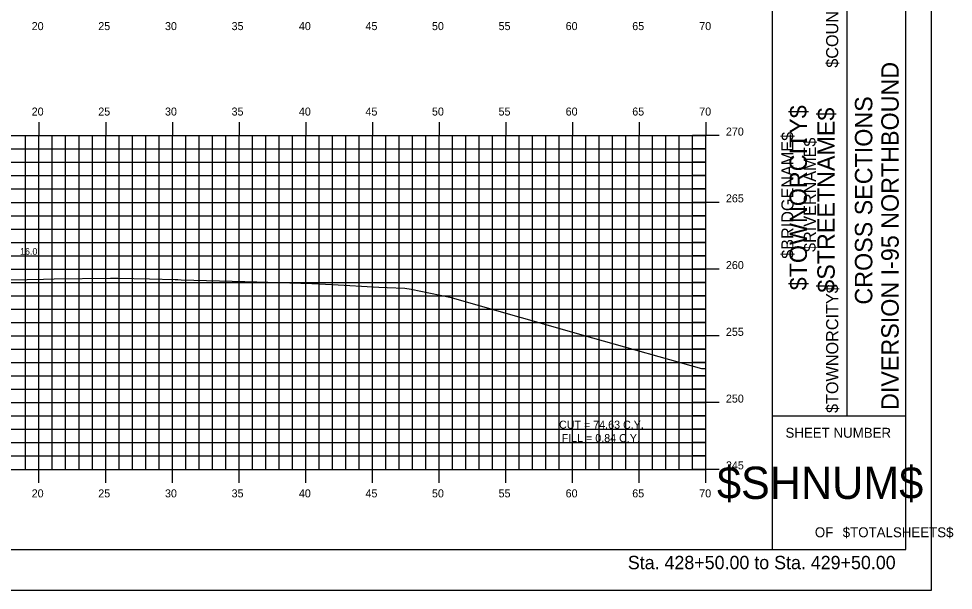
# Model space of a CAD drawing. Extents: x 1160718 to 1173142, y 616002 to 617630.
# Drawn here: x 1171089.7 to 1171159.7, y 616613.9 to 616656.7 of the extents above; entities that cross this region are included whole.
import ezdxf

# ---------------------------------------------------------------- set-up
doc = ezdxf.new("R2010")
doc.units = 0
for name, color, linetype in [('ANNOTATION', 7, 'Continuous'), ('BORDER', 7, 'Continuous'), ('BRIDGE_TITLE', 7, 'Continuous'), ('H_V ANNOTATION', 7, 'Continuous'), ('HIGHWAY_TITLE', 7, 'Continuous'), ('MAJOR', 7, 'Continuous'), ('MINOR', 7, 'Continuous'), ('PLOT BOUNDARY', 7, 'Continuous'), ('S_Roadway_Centerline', 7, 'Continuous')]:
    doc.layers.add(name, color=color, linetype=linetype)

msp = doc.modelspace()

# ---------------------------------------------------------------- linework, layer by layer
at = {"layer": 'BORDER'}
for p, q in [((1171146.177, 616616.931), (1171146.177, 616721.931)), ((1171156.177, 616616.931), (1171156.177, 616721.931)), ((1171151.768, 616626.931), (1171151.768, 616661.931)), ((1171146.177, 616626.931), (1171156.177, 616626.931)), ((1170996.177, 616616.928), (1171156.177, 616616.928))]:
    msp.add_line(p, q, dxfattribs=at)
at = {"layer": 'MAJOR'}
for p, q in [((1171091.177, 616648.93), (1171091.177, 616647.928)), ((1171096.177, 616648.93), (1171096.177, 616647.928)), ((1171101.177, 616648.93), (1171101.177, 616647.928)), ((1171106.177, 616648.93), (1171106.177, 616647.928)), ((1171111.177, 616648.93), (1171111.177, 616647.928)), ((1171116.177, 616648.93), (1171116.177, 616647.928)), ((1171121.177, 616648.93), (1171121.177, 616647.928)), ((1171126.177, 616648.93), (1171126.177, 616647.928)), ((1171131.177, 616648.93), (1171131.177, 616647.928)), ((1171136.177, 616648.93), (1171136.177, 616647.928)), ((1171141.177, 616648.93), (1171141.177, 616647.928)), ((1171001.177, 616647.928), (1171141.177, 616647.928)), ((1171001.177, 616647.928), (1171141.177, 616647.928)), ((1171091.177, 616622.928), (1171091.177, 616647.928)), ((1171096.177, 616622.928), (1171096.177, 616647.928)), ((1171101.177, 616622.928), (1171101.177, 616647.928)), ((1171106.177, 616622.928), (1171106.177, 616647.928)), ((1171111.177, 616622.928), (1171111.177, 616647.928)), ((1171116.177, 616622.928), (1171116.177, 616647.928)), ((1171121.177, 616622.928), (1171121.177, 616647.928)), ((1171126.177, 616622.928), (1171126.177, 616647.928)), ((1171131.177, 616622.928), (1171131.177, 616647.928)), ((1171136.177, 616622.928), (1171136.177, 616647.928)), ((1171142.179, 616647.928), (1171140.175, 616647.928)), ((1171141.177, 616622.928), (1171141.177, 616647.928)), ((1171141.177, 616622.928), (1171141.177, 616647.928)), ((1171001.177, 616642.928), (1171141.177, 616642.928)), ((1171142.179, 616642.928), (1171140.175, 616642.928)), ((1171001.177, 616637.928), (1171141.177, 616637.928)), ((1171142.179, 616637.928), (1171140.175, 616637.928)), ((1171001.177, 616632.928), (1171141.177, 616632.928)), ((1171142.179, 616632.928), (1171140.175, 616632.928)), ((1171001.177, 616627.928), (1171141.177, 616627.928)), ((1171142.179, 616627.928), (1171140.175, 616627.928)), ((1171001.177, 616622.928), (1171141.177, 616622.928)), ((1171001.177, 616622.928), (1171141.177, 616622.928)), ((1171091.177, 616621.926), (1171091.177, 616622.928)), ((1171096.177, 616621.926), (1171096.177, 616622.928)), ((1171101.177, 616621.926), (1171101.177, 616622.928)), ((1171106.177, 616621.926), (1171106.177, 616622.928)), ((1171111.177, 616621.926), (1171111.177, 616622.928)), ((1171116.177, 616621.926), (1171116.177, 616622.928)), ((1171121.177, 616621.926), (1171121.177, 616622.928)), ((1171126.177, 616621.926), (1171126.177, 616622.928)), ((1171131.177, 616621.926), (1171131.177, 616622.928)), ((1171136.177, 616621.926), (1171136.177, 616622.928)), ((1171142.179, 616622.928), (1171140.175, 616622.928)), ((1171141.177, 616621.926), (1171141.177, 616622.928))]:
    msp.add_line(p, q, dxfattribs=at)
at = {"layer": 'MINOR'}
for p, q in [((1171090.177, 616622.928), (1171090.177, 616647.928)), ((1171092.177, 616622.928), (1171092.177, 616647.928)), ((1171093.177, 616622.928), (1171093.177, 616647.928)), ((1171094.177, 616622.928), (1171094.177, 616647.928)), ((1171095.177, 616622.928), (1171095.177, 616647.928)), ((1171097.177, 616622.928), (1171097.177, 616647.928)), ((1171098.177, 616622.928), (1171098.177, 616647.928)), ((1171099.177, 616622.928), (1171099.177, 616647.928)), ((1171100.177, 616622.928), (1171100.177, 616647.928)), ((1171102.177, 616622.928), (1171102.177, 616647.928)), ((1171103.177, 616622.928), (1171103.177, 616647.928)), ((1171104.177, 616622.928), (1171104.177, 616647.928)), ((1171105.177, 616622.928), (1171105.177, 616647.928)), ((1171107.177, 616622.928), (1171107.177, 616647.928)), ((1171108.177, 616622.928), (1171108.177, 616647.928)), ((1171109.177, 616622.928), (1171109.177, 616647.928)), ((1171110.177, 616622.928), (1171110.177, 616647.928)), ((1171112.177, 616622.928), (1171112.177, 616647.928)), ((1171113.177, 616622.928), (1171113.177, 616647.928)), ((1171114.177, 616622.928), (1171114.177, 616647.928)), ((1171115.177, 616622.928), (1171115.177, 616647.928)), ((1171117.177, 616622.928), (1171117.177, 616647.928)), ((1171118.177, 616622.928), (1171118.177, 616647.928)), ((1171119.177, 616622.928), (1171119.177, 616647.928)), ((1171120.177, 616622.928), (1171120.177, 616647.928)), ((1171122.177, 616622.928), (1171122.177, 616647.928)), ((1171123.177, 616622.928), (1171123.177, 616647.928)), ((1171124.177, 616622.928), (1171124.177, 616647.928)), ((1171125.177, 616622.928), (1171125.177, 616647.928)), ((1171127.177, 616622.928), (1171127.177, 616647.928)), ((1171128.177, 616622.928), (1171128.177, 616647.928)), ((1171129.177, 616622.928), (1171129.177, 616647.928)), ((1171130.177, 616622.928), (1171130.177, 616647.928)), ((1171132.177, 616622.928), (1171132.177, 616647.928)), ((1171133.177, 616622.928), (1171133.177, 616647.928)), ((1171134.177, 616622.928), (1171134.177, 616647.928)), ((1171135.177, 616622.928), (1171135.177, 616647.928)), ((1171137.177, 616622.928), (1171137.177, 616647.928)), ((1171138.177, 616622.928), (1171138.177, 616647.928)), ((1171139.177, 616622.928), (1171139.177, 616647.928)), ((1171140.177, 616622.928), (1171140.177, 616647.928)), ((1171001.177, 616646.928), (1171141.177, 616646.928)), ((1171141.177, 616646.928), (1171140.175, 616646.928)), ((1171001.177, 616645.928), (1171141.177, 616645.928)), ((1171141.177, 616645.928), (1171140.175, 616645.928)), ((1171001.177, 616644.928), (1171141.177, 616644.928)), ((1171141.177, 616644.928), (1171140.175, 616644.928)), ((1171001.177, 616643.928), (1171141.177, 616643.928)), ((1171141.177, 616643.928), (1171140.175, 616643.928)), ((1171001.177, 616641.928), (1171141.177, 616641.928)), ((1171141.177, 616641.928), (1171140.175, 616641.928)), ((1171001.177, 616640.928), (1171141.177, 616640.928)), ((1171141.177, 616640.928), (1171140.175, 616640.928)), ((1171001.177, 616639.928), (1171141.177, 616639.928)), ((1171141.177, 616639.928), (1171140.175, 616639.928)), ((1171001.177, 616638.928), (1171141.177, 616638.928)), ((1171141.177, 616638.928), (1171140.175, 616638.928)), ((1171001.177, 616636.928), (1171141.177, 616636.928)), ((1171141.177, 616636.928), (1171140.175, 616636.928)), ((1171001.177, 616635.928), (1171141.177, 616635.928)), ((1171141.177, 616635.928), (1171140.175, 616635.928)), ((1171001.177, 616634.928), (1171141.177, 616634.928)), ((1171141.177, 616634.928), (1171140.175, 616634.928)), ((1171001.177, 616633.928), (1171141.177, 616633.928)), ((1171141.177, 616633.928), (1171140.175, 616633.928)), ((1171001.177, 616631.928), (1171141.177, 616631.928)), ((1171141.177, 616631.928), (1171140.175, 616631.928)), ((1171001.177, 616630.928), (1171141.177, 616630.928)), ((1171141.177, 616630.928), (1171140.175, 616630.928)), ((1171001.177, 616629.928), (1171141.177, 616629.928)), ((1171141.177, 616629.928), (1171140.175, 616629.928)), ((1171001.177, 616628.928), (1171141.177, 616628.928)), ((1171141.177, 616628.928), (1171140.175, 616628.928)), ((1171001.177, 616626.928), (1171141.177, 616626.928)), ((1171141.177, 616626.928), (1171140.175, 616626.928)), ((1171001.177, 616625.928), (1171141.177, 616625.928)), ((1171141.177, 616625.928), (1171140.175, 616625.928)), ((1171001.177, 616624.928), (1171141.177, 616624.928)), ((1171141.177, 616624.928), (1171140.175, 616624.928)), ((1171001.177, 616623.928), (1171141.177, 616623.928)), ((1171141.177, 616623.928), (1171140.175, 616623.928))]:
    msp.add_line(p, q, dxfattribs=at)
at = {"layer": 'PLOT BOUNDARY'}
msp.add_lwpolyline([(1170988.084, 616613.869), (1171158.084, 616613.869), (1171158.084, 616723.869), (1170988.084, 616723.869)], close=True, dxfattribs=at)
at = {"layer": 'S_Roadway_Centerline'}
msp.add_lwpolyline([(1171087.785, 616637.11), (1171091.512, 616637.181), (1171092.311, 616637.192), (1171096.543, 616637.252), (1171096.558, 616637.252), (1171096.837, 616637.253), (1171097.091, 616637.246), (1171099.453, 616637.189), (1171101.389, 616637.142), (1171101.574, 616637.136), (1171101.843, 616637.129), (1171106.606, 616637.001), (1171107.511, 616636.976), (1171111.637, 616636.852), (1171113.181, 616636.765), (1171116.668, 616636.572), (1171117.287, 616636.551), (1171118.614, 616636.507), (1171119.087, 616636.417), (1171121.977, 616635.824), (1171132.685, 616632.787), (1171140.846, 616630.486), (1171141.177, 616630.47)], dxfattribs=at)

# ---------------------------------------------------------------- texts
at = {"layer": 'ANNOTATION'}
msp.add_text("16.0'", height=0.5, dxfattribs=at).set_placement((1171089.755, 616638.999))
for s, p in [('CUT = 74.63 C.Y.', (1171130.168, 616625.978)), ('FILL = 0.84 C.Y.', (1171130.364, 616624.976))]:
    msp.add_text(s, height=0.6, rotation=359.92408, dxfattribs=at).set_placement(p)
at = {"layer": 'BORDER'}
for s, height, rotation, p in [('DIVERSION I-95 NORTHBOUND  ', 1.30428, 90, (1171155.631, 616627.379)), ('CROSS SECTIONS', 1.30428, 90, (1171153.653, 616635.27)), ('SHEET NUMBER', 0.74527, 360, (1171147.142, 616625.295)), ('$SHNUM$', 2.4194, 360, (1171142.01, 616620.711)), ('OF', 0.7453, 360, (1171149.344, 616617.841)), ('$TOTALSHEETS$', 0.74527, 360, (1171151.433, 616617.841))]:
    msp.add_text(s, height=height, rotation=rotation, dxfattribs=at).set_placement(p)
at = {"layer": 'BRIDGE_TITLE'}
for s, height, p in [('$COUNTY$', 0.9072, (1171151.097, 616653.011)), ('$BRIDGENAME$', 0.90716, (1171147.743, 616638.7)), ('$RIVERNAME$', 0.90716, (1171149.42, 616639.214)), ('$TOWNORCITY$', 0.90716, (1171151.097, 616627.152))]:
    msp.add_text(s, height=height, rotation=90, dxfattribs=at).set_placement(p)
at = {"layer": 'H_V ANNOTATION'}
for s, height, p in [('20', 0.6, (1171090.631, 616655.828)), ('25', 0.6, (1171095.623, 616655.828)), ('30', 0.6, (1171100.625, 616655.828)), ('35', 0.6, (1171105.617, 616655.828)), ('40', 0.6, (1171110.663, 616655.828)), ('45', 0.6, (1171115.655, 616655.828)), ('50', 0.6, (1171120.641, 616655.828)), ('55', 0.6, (1171125.633, 616655.828)), ('60', 0.6, (1171130.663, 616655.828)), ('65', 0.6, (1171135.655, 616655.828)), ('70', 0.6, (1171140.679, 616655.828)), ('20', 0.6, (1171090.631, 616649.428)), ('25', 0.6, (1171095.623, 616649.428)), ('30', 0.6, (1171100.625, 616649.428)), ('35', 0.6, (1171105.617, 616649.428)), ('40', 0.6, (1171110.663, 616649.428)), ('45', 0.6, (1171115.655, 616649.428)), ('50', 0.6, (1171120.641, 616649.428)), ('55', 0.6, (1171125.633, 616649.428)), ('60', 0.6, (1171130.663, 616649.428)), ('65', 0.6, (1171135.655, 616649.428)), ('70', 0.6, (1171140.679, 616649.428)), ('270', 0.6, (1171142.677, 616647.928)), ('265', 0.6, (1171142.677, 616642.928)), ('260', 0.6, (1171142.677, 616637.928)), ('255', 0.6, (1171142.677, 616632.928)), ('250', 0.6, (1171142.677, 616627.928)), ('245', 0.6, (1171142.677, 616622.928)), ('20', 0.6, (1171090.631, 616620.828)), ('25', 0.6, (1171095.623, 616620.828)), ('30', 0.6, (1171100.625, 616620.828)), ('35', 0.6, (1171105.617, 616620.828)), ('40', 0.6, (1171110.663, 616620.828)), ('45', 0.6, (1171115.655, 616620.828)), ('50', 0.6, (1171120.641, 616620.828)), ('55', 0.6, (1171125.633, 616620.828)), ('60', 0.6, (1171130.663, 616620.828)), ('65', 0.6, (1171135.655, 616620.828)), ('70', 0.6, (1171140.679, 616620.828)), ('Sta. 428+50.00 to Sta. 429+50.00', 1.0002, (1171135.323, 616615.448))]:
    msp.add_text(s, height=height, dxfattribs=at).set_placement(p)
at = {"layer": 'HIGHWAY_TITLE'}
for s, p in [('$TOWNORCITY$', (1171148.749, 616636.34)), ('$STREETNAME$', (1171150.836, 616636.16))]:
    msp.add_text(s, height=1.30428, rotation=90, dxfattribs=at).set_placement(p)

doc.saveas('drawing.dxf')
